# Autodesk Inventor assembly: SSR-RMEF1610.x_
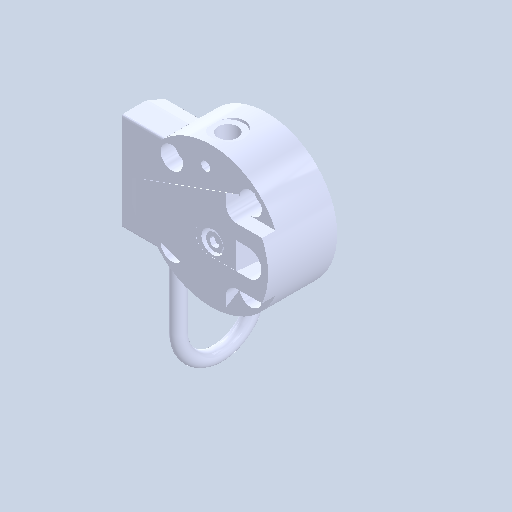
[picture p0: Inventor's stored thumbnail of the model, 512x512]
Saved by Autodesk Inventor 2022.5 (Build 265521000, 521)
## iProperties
Created: 2024-09
Part Number: SSR-RMEF1610.x_
Document SubType Name: Assembly
Designer: ImaoCorp
Author: ImaoCorp
Sending System: SOLIDWORKS 2022-2022290
MC: AMD64
MC_MODEL: Intel64 Family 6 Model 60 Stepping 3, GenuineIntel
OS: Windows_NT
FRU: Parasolid Version 33.1, build 260,  4-25-2022
FORMAT: text
GUISE: transmit
KEY: FILESSR-RMEF1610.x_t
DATE: Wed Sep 11 11:57:08 2024
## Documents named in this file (3)
- Y:\5.更新分\2024年対応\0911_SSR-RM\ssr-rmef1610\SSR-RMEF1610.x_.iam
- Y:\5.更新分\2024年対応\0911_SSR-RM\ssr-rmef1610\SSR-RMEF1610_01.ipt
- Y:\5.更新分\2024年対応\0911_SSR-RM\ssr-rmef1610\SSR-RMEF1610_02.ipt
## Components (2 placed, 2 different names)
1. SSR-RMEF1610_01
2. SSR-RMEF1610_02
